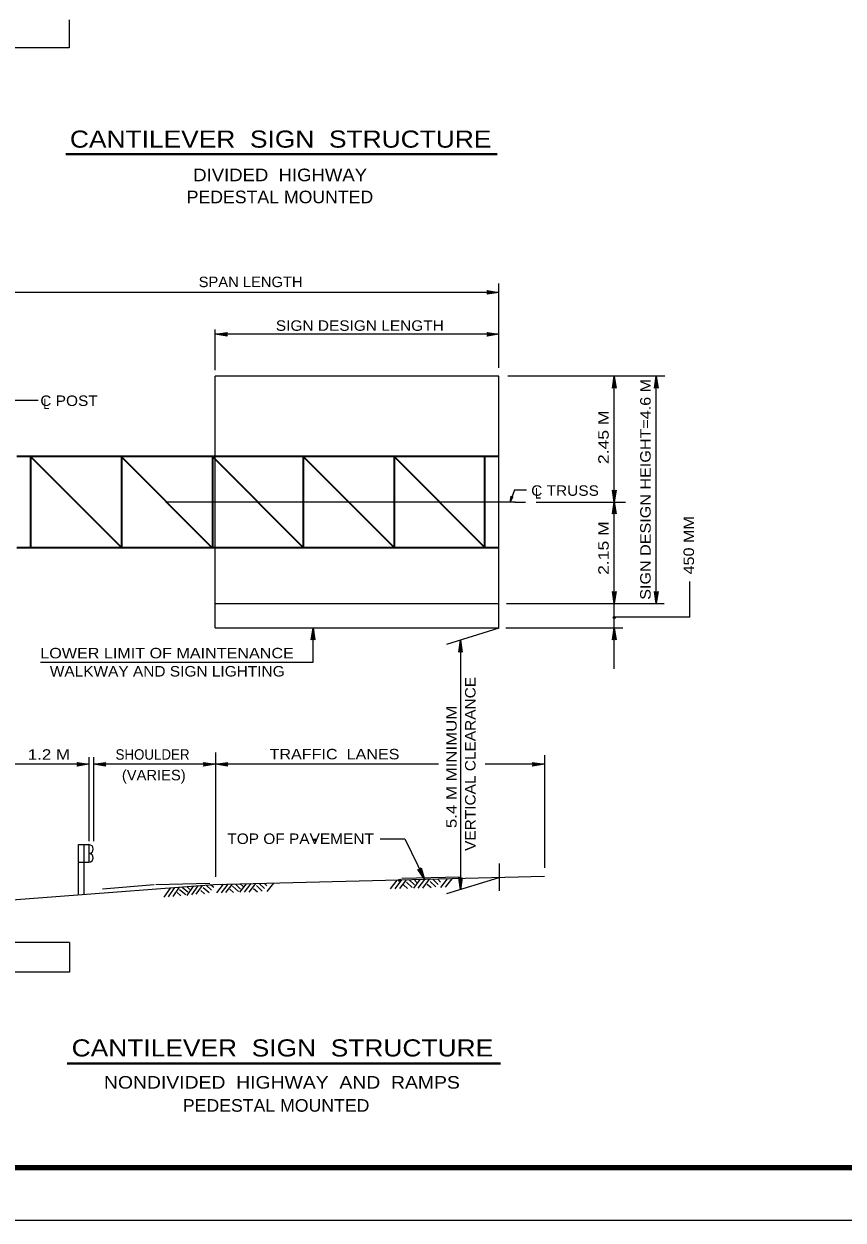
# Model space of a CAD drawing. Extents: x 312601.858 to 312602.699, y 144420.109 to 144420.704.
# Drawn here: x 312601.9947 to 312602.229, y 144420.1095 to 144420.4517 of the extents above; entities that cross this region are included whole.
import ezdxf
from ezdxf.enums import TextEntityAlignment as Align

# ---------------------------------------------------------------- set-up
doc = ezdxf.new("R2010")
doc.units = 0
doc.header["$LTSCALE"] = 0.0012
doc.header["$PDMODE"] = 32
doc.header["$PDSIZE"] = 0.0006
doc.linetypes.add('DOT_DASHED', pattern=[7.7, 5, -1.2, 0.3, -1.2])
doc.linetypes.add('LONG_DASHED', pattern=[7.5, 6, -1.5])
doc.layers.add('1', color=7, linetype='Continuous', lineweight=13)
doc.layers.add('39', color=7, linetype='Continuous', lineweight=13)

msp = doc.modelspace()

# ---------------------------------------------------------------- hatches: boundary and pattern name
at = {"layer": '39'}
for points in [[(312602.1275, 144420.3749), (312602.1272, 144420.3754), (312602.1306, 144420.3749), (312602.1272, 144420.3744)], [(312602.0525, 144420.3629), (312602.0528, 144420.3624), (312602.0494, 144420.3629), (312602.0528, 144420.3634)], [(312602.1275, 144420.3629), (312602.1272, 144420.3634), (312602.1306, 144420.3629), (312602.1272, 144420.3624)], [(312602.1636, 144420.3478), (312602.1631, 144420.3475), (312602.1636, 144420.3509), (312602.1641, 144420.3475)], [(312602.1636, 144420.3478), (312602.1631, 144420.3475), (312602.1636, 144420.3509), (312602.1641, 144420.3475)], [(312602.1636, 144420.3478), (312602.1631, 144420.3475), (312602.1636, 144420.3509), (312602.1641, 144420.3475)], [(312602.1756, 144420.3478), (312602.1751, 144420.3475), (312602.1756, 144420.3509), (312602.1761, 144420.3475)], [(312602.1756, 144420.3478), (312602.1751, 144420.3475), (312602.1756, 144420.3509), (312602.1761, 144420.3475)], [(312602.1756, 144420.3478), (312602.1751, 144420.3475), (312602.1756, 144420.3509), (312602.1761, 144420.3475)], [(312602.1343, 144420.3164), (312602.1346, 144420.3164), (312602.1338, 144420.3149), (312602.1341, 144420.3166)], [(312602.1636, 144420.318), (312602.1641, 144420.3183), (312602.1636, 144420.3149), (312602.1631, 144420.3183)], [(312602.1636, 144420.318), (312602.1641, 144420.3183), (312602.1636, 144420.3149), (312602.1631, 144420.3183)], [(312602.1636, 144420.3118), (312602.1631, 144420.3115), (312602.1636, 144420.3149), (312602.1641, 144420.3115)], [(312602.1636, 144420.3118), (312602.1631, 144420.3115), (312602.1636, 144420.3149), (312602.1641, 144420.3115)], [(312602.1636, 144420.289), (312602.1641, 144420.2893), (312602.1636, 144420.2859), (312602.1631, 144420.2893)], [(312602.1636, 144420.289), (312602.1641, 144420.2893), (312602.1636, 144420.2859), (312602.1631, 144420.2893)], [(312602.1756, 144420.289), (312602.1761, 144420.2893), (312602.1756, 144420.2859), (312602.1751, 144420.2893)], [(312602.1756, 144420.289), (312602.1761, 144420.2893), (312602.1756, 144420.2859), (312602.1751, 144420.2893)], [(312602.1756, 144420.289), (312602.1761, 144420.2893), (312602.1756, 144420.2859), (312602.1751, 144420.2893)], [(312602.1636, 144420.2816, 1), (312602.1636, 144420.2822, 1)], [(312602.0774, 144420.2758), (312602.0769, 144420.2755), (312602.0774, 144420.2789), (312602.0779, 144420.2755)], [(312602.0774, 144420.2758), (312602.0769, 144420.2755), (312602.0774, 144420.2789), (312602.0779, 144420.2755)], [(312602.0774, 144420.2758), (312602.0769, 144420.2755), (312602.0774, 144420.2789), (312602.0779, 144420.2755)], [(312602.1636, 144420.2758), (312602.1631, 144420.2755), (312602.1636, 144420.2789), (312602.1641, 144420.2755)], [(312602.1196, 144420.2723), (312602.1191, 144420.272), (312602.1196, 144420.2754), (312602.1201, 144420.272)], [(312602.0102, 144420.2399), (312602.0099, 144420.2404), (312602.0133, 144420.2399), (312602.0099, 144420.2394)], [(312602.0177, 144420.2399), (312602.018, 144420.2394), (312602.0146, 144420.2399), (312602.018, 144420.2404)], [(312602.0464, 144420.2399), (312602.0461, 144420.2404), (312602.0495, 144420.2399), (312602.0461, 144420.2394)], [(312602.0526, 144420.2399), (312602.0529, 144420.2394), (312602.0495, 144420.2399), (312602.0529, 144420.2404)], [(312602.1405, 144420.2399), (312602.1402, 144420.2404), (312602.1436, 144420.2399), (312602.1402, 144420.2394)], [(312602.1405, 144420.2399), (312602.1402, 144420.2404), (312602.1436, 144420.2399), (312602.1402, 144420.2394)], [(312602.108, 144420.2098), (312602.1083, 144420.2103), (312602.1093, 144420.207), (312602.1074, 144420.2098)], [(312602.1196, 144420.2071), (312602.1201, 144420.2074), (312602.1196, 144420.204), (312602.1191, 144420.2074)]]:
    msp.add_hatch(color=256, dxfattribs=at).paths.add_polyline_path(points)

# ---------------------------------------------------------------- linework, layer by layer
at = {"layer": '1'}
for p, q in [((312602.135, 144420.3184), (312602.1338, 144420.3149)), ((312602.135, 144420.3184), (312602.1385, 144420.3184)), ((312602.1306, 144420.2788), (312602.1156, 144420.2742)), ((312602.0966, 144420.2186), (312602.1037, 144420.2186)), ((312602.1037, 144420.2186), (312602.1093, 144420.207)), ((312602.0996, 144420.2043), (312602.1015, 144420.2067)), ((312602.1009, 144420.2043), (312602.1028, 144420.2068)), ((312602.1022, 144420.2044), (312602.1041, 144420.2068)), ((312602.1028, 144420.2073), (312602.1195, 144420.2077)), ((312602.1041, 144420.2062), (312602.1058, 144420.2046)), ((312602.1049, 144420.2068), (312602.1064, 144420.2054)), ((312602.1062, 144420.2045), (312602.1081, 144420.2069)), ((312602.1063, 144420.2069), (312602.1071, 144420.2061)), ((312602.1075, 144420.2045), (312602.1094, 144420.2069)), ((312602.1088, 144420.2045), (312602.1107, 144420.207)), ((312602.1109, 144420.2064), (312602.1125, 144420.2048)), ((312602.1117, 144420.207), (312602.1132, 144420.2055)), ((312602.1131, 144420.207), (312602.1139, 144420.2062)), ((312602.114, 144420.2046), (312602.1159, 144420.2071)), ((312602.1153, 144420.2047), (312602.1172, 144420.2071)), ((312602.1306, 144420.2074), (312602.1156, 144420.2028)), ((312602.0172, 144420.2043), (312602.032, 144420.2055)), ((312602.0324, 144420.2055), (312602.0479, 144420.2059)), ((312602.0348, 144420.2019), (312602.0366, 144420.2045)), ((312602.0361, 144420.202), (312602.0379, 144420.2046)), ((312602.0374, 144420.2021), (312602.0392, 144420.2047)), ((312602.0385, 144420.2032), (312602.0396, 144420.2023)), ((312602.0392, 144420.2041), (312602.041, 144420.2026)), ((312602.04, 144420.2047), (312602.0416, 144420.2034)), ((312602.0414, 144420.2024), (312602.0432, 144420.205)), ((312602.0414, 144420.2048), (312602.0422, 144420.2041)), ((312602.0427, 144420.2025), (312602.0445, 144420.2051)), ((312602.044, 144420.2027), (312602.0458, 144420.2052)), ((312602.0453, 144420.2038), (312602.0464, 144420.2028)), ((312602.046, 144420.2046), (312602.0477, 144420.2032)), ((312602.0468, 144420.2053), (312602.0484, 144420.2039)), ((312602.0482, 144420.2054), (312602.049, 144420.2047)), ((312602.0499, 144420.2031), (312602.0518, 144420.2056)), ((312602.0512, 144420.2031), (312602.0531, 144420.2056)), ((312602.0525, 144420.2032), (312602.0544, 144420.2056)), ((312602.0536, 144420.2042), (312602.0547, 144420.2032)), ((312602.0544, 144420.205), (312602.0561, 144420.2035)), ((312602.0552, 144420.2056), (312602.0567, 144420.2042)), ((312602.0565, 144420.2033), (312602.0584, 144420.2057)), ((312602.0566, 144420.2057), (312602.0574, 144420.2049)), ((312602.0578, 144420.2033), (312602.0597, 144420.2058)), ((312602.0591, 144420.2033), (312602.061, 144420.2058)), ((312602.0604, 144420.2044), (312602.0615, 144420.2034)), ((312602.0612, 144420.2052), (312602.0629, 144420.2036)), ((312602.062, 144420.2058), (312602.0635, 144420.2044)), ((312602.0634, 144420.2059), (312602.0642, 144420.2051)), ((312602.0643, 144420.2035), (312602.0662, 144420.2059)), ((312602.1033, 144420.2054), (312602.1044, 144420.2044)), ((312602.1101, 144420.2056), (312602.1112, 144420.2046))]:
    msp.add_line(p, q, dxfattribs=at)
at = {"layer": '1', "lineweight": 25}
msp.add_lwpolyline([(312601.8578, 144420.1095), (312602.6988, 144420.1095), (312602.6988, 144420.7035)], dxfattribs=at)
at = {"layer": '1'}
for p in [(312602.0779, 144420.2183), (312602.1022, 144420.2067)]:
    msp.add_point(p, dxfattribs=at)
at = {"layer": '39', "linetype": 'LONG_DASHED', "lineweight": 25}
for p, q in [((312602.0076, 144420.4529), (312602.0076, 144420.4449)), ((312602.0076, 144420.4449), (312601.9656, 144420.4449)), ((312602.1306, 144420.3509), (312602.0494, 144420.3509)), ((312602.0494, 144420.2789), (312602.0494, 144420.3509)), ((312602.1306, 144420.2789), (312602.1306, 144420.3509)), ((312602.0494, 144420.2859), (312602.1306, 144420.2859)), ((312602.0494, 144420.2789), (312602.1306, 144420.2789)), ((312602.0077, 144420.1889), (312601.9656, 144420.1889)), ((312602.0077, 144420.1889), (312602.0077, 144420.1804)), ((312602.0077, 144420.1804), (312601.9656, 144420.1804))]:
    msp.add_line(p, q, dxfattribs=at)
at = {"layer": '39', "lineweight": 40}
for p, q in [((312602.0067, 144420.4144), (312602.1301, 144420.4144)), ((312602.0071, 144420.1543), (312602.131, 144420.1543))]:
    msp.add_line(p, q, dxfattribs=at)
at = {"layer": '39'}
for p, q in [((312602.1306, 144420.3533), (312602.1306, 144420.3774)), ((312602.1306, 144420.3749), (312601.9866, 144420.3749)), ((312602.0494, 144420.3526), (312602.0494, 144420.3643)), ((312602.1306, 144420.3629), (312602.0494, 144420.3629)), ((312602.1781, 144420.3509), (312602.1331, 144420.3509)), ((312602.1636, 144420.3149), (312602.1636, 144420.3509)), ((312602.1756, 144420.2859), (312602.1756, 144420.3509)), ((312601.9988, 144420.344), (312601.9866, 144420.344)), ((312602.1266, 144420.3279), (312602.1266, 144420.3019)), ((312602.1412, 144420.3149), (312602.1668, 144420.3149)), ((312602.1636, 144420.2859), (312602.1636, 144420.3149)), ((312602.1852, 144420.282), (312602.1852, 144420.2922)), ((312602.1852, 144420.282), (312602.1636, 144420.282)), ((312602.1326, 144420.2789), (312602.166, 144420.2789)), ((312602.1196, 144420.2754), (312602.1196, 144420.204)), ((312602.0133, 144420.2419), (312602.0133, 144420.2179)), ((312602.0146, 144420.2419), (312602.0146, 144420.2179)), ((312602.0495, 144420.2433), (312602.0495, 144420.2077)), ((312602.1436, 144420.2425), (312602.1436, 144420.2103)), ((312602.0133, 144420.2399), (312601.9896, 144420.2399)), ((312602.0495, 144420.2399), (312602.0146, 144420.2399)), ((312602.1133, 144420.2399), (312602.0495, 144420.2399)), ((312602.1436, 144420.2399), (312602.1267, 144420.2399)), ((312602.0118, 144420.2169), (312602.0118, 144420.2039)), ((312602.1308, 144420.2037), (312602.1308, 144420.2115))]:
    msp.add_line(p, q, dxfattribs=at)
at = {"layer": '39', "lineweight": 35}
for p, q in [((312602.1306, 144420.3279), (312601.9927, 144420.3279)), ((312601.9966, 144420.3279), (312601.9966, 144420.3019)), ((312602.0226, 144420.3019), (312601.9966, 144420.3279)), ((312602.0485, 144420.3019), (312602.0225, 144420.3279)), ((312602.0226, 144420.3279), (312602.0226, 144420.3019)), ((312602.0486, 144420.3279), (312602.0486, 144420.3019)), ((312602.0746, 144420.3019), (312602.0486, 144420.3279)), ((312602.0746, 144420.3279), (312602.0746, 144420.3019)), ((312602.1006, 144420.3019), (312602.0746, 144420.3279)), ((312602.1006, 144420.3279), (312602.1006, 144420.3019)), ((312602.1266, 144420.3019), (312602.1006, 144420.3279)), ((312602.1266, 144420.3019), (312602.1266, 144420.3279)), ((312601.9927, 144420.3019), (312602.1306, 144420.3019))]:
    msp.add_line(p, q, dxfattribs=at)
at = {"layer": '39', "linetype": 'DOT_DASHED'}
for p, q in [((312602.1352, 144420.3149), (312601.9799, 144420.3149)), ((312602.1351, 144420.3149), (312602.1382, 144420.3149))]:
    msp.add_line(p, q, dxfattribs=at)
at = {"layer": '39', "lineweight": 25}
for p, q in [((312602.0103, 144420.2026), (312602.0103, 144420.2169)), ((312602.0118, 144420.2169), (312602.0118, 144420.2027)), ((312602.0103, 144420.2119), (312602.0133, 144420.2119)), ((312602.0103, 144420.2119), (312602.0133, 144420.2119))]:
    msp.add_line(p, q, dxfattribs=at)
at = {"layer": '39', "lineweight": 158}
msp.add_line((312601.9088, 144420.1245), (312602.6838, 144420.1245), dxfattribs=at)
at = {"layer": '39'}
for points in [[(312602.1275, 144420.3749), (312602.1272, 144420.3754), (312602.1306, 144420.3749), (312602.1272, 144420.3744)], [(312602.0525, 144420.3629), (312602.0528, 144420.3624), (312602.0494, 144420.3629), (312602.0528, 144420.3634)], [(312602.1275, 144420.3629), (312602.1272, 144420.3634), (312602.1306, 144420.3629), (312602.1272, 144420.3624)], [(312602.1636, 144420.3478), (312602.1631, 144420.3475), (312602.1636, 144420.3509), (312602.1641, 144420.3475)], [(312602.1636, 144420.3478), (312602.1631, 144420.3475), (312602.1636, 144420.3509), (312602.1641, 144420.3475)], [(312602.1636, 144420.3478), (312602.1631, 144420.3475), (312602.1636, 144420.3509), (312602.1641, 144420.3475)], [(312602.1756, 144420.3478), (312602.1751, 144420.3475), (312602.1756, 144420.3509), (312602.1761, 144420.3475)], [(312602.1756, 144420.3478), (312602.1751, 144420.3475), (312602.1756, 144420.3509), (312602.1761, 144420.3475)], [(312602.1756, 144420.3478), (312602.1751, 144420.3475), (312602.1756, 144420.3509), (312602.1761, 144420.3475)], [(312602.1343, 144420.3164), (312602.1346, 144420.3164), (312602.1338, 144420.3149), (312602.1341, 144420.3166)], [(312602.1636, 144420.318), (312602.1641, 144420.3183), (312602.1636, 144420.3149), (312602.1631, 144420.3183)], [(312602.1636, 144420.318), (312602.1641, 144420.3183), (312602.1636, 144420.3149), (312602.1631, 144420.3183)], [(312602.1636, 144420.3118), (312602.1631, 144420.3115), (312602.1636, 144420.3149), (312602.1641, 144420.3115)], [(312602.1636, 144420.3118), (312602.1631, 144420.3115), (312602.1636, 144420.3149), (312602.1641, 144420.3115)], [(312602.1636, 144420.289), (312602.1641, 144420.2893), (312602.1636, 144420.2859), (312602.1631, 144420.2893)], [(312602.1636, 144420.289), (312602.1641, 144420.2893), (312602.1636, 144420.2859), (312602.1631, 144420.2893)], [(312602.1756, 144420.289), (312602.1761, 144420.2893), (312602.1756, 144420.2859), (312602.1751, 144420.2893)], [(312602.1756, 144420.289), (312602.1761, 144420.2893), (312602.1756, 144420.2859), (312602.1751, 144420.2893)], [(312602.1756, 144420.289), (312602.1761, 144420.2893), (312602.1756, 144420.2859), (312602.1751, 144420.2893)], [(312602.0774, 144420.2758), (312602.0769, 144420.2755), (312602.0774, 144420.2789), (312602.0779, 144420.2755)], [(312602.0774, 144420.2758), (312602.0769, 144420.2755), (312602.0774, 144420.2789), (312602.0779, 144420.2755)], [(312602.0774, 144420.2758), (312602.0769, 144420.2755), (312602.0774, 144420.2789), (312602.0779, 144420.2755)], [(312602.1636, 144420.2758), (312602.1631, 144420.2755), (312602.1636, 144420.2789), (312602.1641, 144420.2755)], [(312602.1196, 144420.2723), (312602.1191, 144420.272), (312602.1196, 144420.2754), (312602.1201, 144420.272)], [(312602.0102, 144420.2399), (312602.0099, 144420.2404), (312602.0133, 144420.2399), (312602.0099, 144420.2394)], [(312602.0177, 144420.2399), (312602.018, 144420.2394), (312602.0146, 144420.2399), (312602.018, 144420.2404)], [(312602.0464, 144420.2399), (312602.0461, 144420.2404), (312602.0495, 144420.2399), (312602.0461, 144420.2394)], [(312602.0526, 144420.2399), (312602.0529, 144420.2394), (312602.0495, 144420.2399), (312602.0529, 144420.2404)], [(312602.1405, 144420.2399), (312602.1402, 144420.2404), (312602.1436, 144420.2399), (312602.1402, 144420.2394)], [(312602.1405, 144420.2399), (312602.1402, 144420.2404), (312602.1436, 144420.2399), (312602.1402, 144420.2394)], [(312602.108, 144420.2098), (312602.1083, 144420.2103), (312602.1093, 144420.207), (312602.1074, 144420.2098)], [(312602.1196, 144420.2071), (312602.1201, 144420.2074), (312602.1196, 144420.204), (312602.1191, 144420.2074)]]:
    msp.add_lwpolyline(points, close=True, dxfattribs=at)
for points in [[(312602.1328, 144420.2859), (312602.1633, 144420.2859), (312602.1779, 144420.2859)], [(312602.1636, 144420.2672), (312602.1636, 144420.2789), (312602.1636, 144420.2859)], [(312601.9994, 144420.2691), (312602.0774, 144420.2691), (312602.0774, 144420.2789)], [(312602.0103, 144420.2169), (312602.0133, 144420.2169), (312602.0133, 144420.2119)]]:
    msp.add_lwpolyline(points, dxfattribs=at)
at = {"layer": '39', "lineweight": 25}
for points in [[(312602.0103, 144420.2169), (312602.0133, 144420.2169), (312602.0133, 144420.2119)], [(312601.9586, 144420.1986), (312602.0489, 144420.2055), (312602.1436, 144420.2079)]]:
    msp.add_lwpolyline(points, dxfattribs=at)
at = {"layer": '39'}
msp.add_circle((312602.1636, 144420.2819), 0.0003, dxfattribs=at)
at = {"layer": '39', "lineweight": 25}
for centre in [(312602.0133, 144420.21565), (312602.0133, 144420.21315)]:
    msp.add_arc(centre, 0.00125, 270, 90, dxfattribs=at)
at = {"layer": '39'}
for centre in [(312602.0133, 144420.21565), (312602.0133, 144420.21315)]:
    msp.add_arc(centre, 0.00125, 270, 90, dxfattribs=at)

# ---------------------------------------------------------------- texts
at = {"layer": '1'}
for s, height, width, p in [('SPAN LENGTH', 0.003, 1.05, (312602.05955, 144420.3764)), ('SIGN DESIGN LENGTH', 0.003, 1.1, (312602.0908, 144420.3639)), ('C POST', 0.003, 1.1, (312602.0076, 144420.3424)), ('L', 0.003, 0.75, (312602.00115, 144420.3415)), ('C TRUSS', 0.003, 1.1, (312602.1495, 144420.3167)), ('L', 0.003, 0.75, (312602.14175, 144420.3159)), ('1.2 M', 0.003, 1.2, (312602.00185, 144420.2412)), ('SHOULDER', 0.003, 0.95, (312602.0315, 144420.2412)), ('(VARIES)', 0.003, 1.05, (312602.03185, 144420.2353)), ('TOP OF PAVEMENT', 0.003, 1.1, (312602.07385, 144420.2171)), ('PEDESTAL MOUNTED', 0.0036, 1.05, (312602.06685, 144420.1405))]:
    msp.add_text(s, height=height, dxfattribs=dict(at, width=width)).set_placement(p, align=Align.CENTER)
for s, width, p in [('2.45 M', 1.25, (312602.162, 144420.33345)), ('2.15 M ', 1.25, (312602.162, 144420.30245)), ('450 MM', 1.15, (312602.1864, 144420.30255)), ('VERTICAL CLEARANCE', 1.1, (312602.1239, 144420.24)), ('5.4 M MINIMUM', 1.2, (312602.1185, 144420.23915))]:
    msp.add_text(s, height=0.003, rotation=90, dxfattribs=dict(at, width=width)).set_placement(p, align=Align.CENTER)
at = {"layer": '39'}
for s, height, width, p in [('CANTILEVER  SIGN  STRUCTURE', 0.0049, 1.15, (312602.06815, 144420.4163)), ('DIVIDED  HIGHWAY', 0.0036, 1.1, (312602.068, 144420.4067)), ('PEDESTAL MOUNTED', 0.0036, 1.05, (312602.06795, 144420.4004)), ('LOWER LIMIT OF MAINTENANCE', 0.003, 1.15, (312602.03565, 144420.2702)), ('WALKWAY AND SIGN LIGHTING', 0.003, 1.1, (312602.0357, 144420.265)), ('TRAFFIC  LANES', 0.003, 1.15, (312602.08355, 144420.2413)), ('CANTILEVER  SIGN  STRUCTURE', 0.0049, 1.15, (312602.06865, 144420.1563)), ('NONDIVIDED  HIGHWAY  AND  RAMPS', 0.0036, 1.15, (312602.0685, 144420.1471))]:
    msp.add_text(s, height=height, dxfattribs=dict(at, width=width)).set_placement(p, align=Align.CENTER)
at = {"layer": '39', "width": 1.15}
msp.add_text('SIGN DESIGN HEIGHT=4.6 M', height=0.003, rotation=90, dxfattribs=at).set_placement((312602.174, 144420.31855), align=Align.CENTER)

doc.saveas('drawing.dxf')
